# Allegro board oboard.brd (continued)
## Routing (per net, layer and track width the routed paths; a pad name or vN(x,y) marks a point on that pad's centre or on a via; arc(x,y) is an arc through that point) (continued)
LVD17: length 33.2
  TOP w0.127: J2.12 v1(60.59,38.06) ; 55,42.05 54.95,42.05 54.85,41.95 54.84,41.95 54.7,41.81 39.95,41.81 38.4,40.26 U1.72
  TOP w0.2: 55,42.05 55.7,42.75 59.6,42.75 59.8,42.55 59.81,42.55 60.65,41.71 v1(60.65,41.17)
  BOTTOM w0.2: v1(60.59,38.06) 60.65,38.12 v1(60.65,41.17)
LVDE: length 25.9
  TOP w0.127: U1.50 43.69,32.12 44.42,31.39 53.67,31.39 55.57,29.49 v1(59.89,29.49)
  TOP w0.2: J2.34 60.39,27.06 59.89,27.56 v1(59.89,28.47)
  BOTTOM w0.18: v1(59.89,28.47) 59.89,28.8
  BOTTOM w0.2: 59.89,28.8 v1(59.89,29.49)
LVSYNC: length 25.1
  TOP w0.127: 60.65,28.73 60.4,28.98 55.57,28.98 53.41,31.14 44.27,31.14 43.69,31.72 U1.49
  TOP w0.2: J2.33 61.9,27.56 61.73,27.39 61.08,27.39 60.65,27.81 60.65,28.73
MIC_BIAS: length 17.9
  TOP w0.127: U1.95 29.2,40.21 28.62,40.79 26.4,40.79
  TOP w0.2: v1(19.51,40.79) 26.4,40.79
  BOTTOM w0.127: R32.1 20.01,47.86 19.51,47.35 19.51,45.85
  BOTTOM w0.2: v1(19.51,40.79) 19.51,45.85
MIC_INN: length 26.5
  TOP w0.127: U1.98 26.31,37.32 25.25,38.38 18.49,38.38 v1(18.11,38.76)
  BOTTOM w0.127: 18.11,39.71 18.11,46.26 18.07,46.3
  BOTTOM w0.2: 18.07,39.75 C46.1 ; 18.07,39.75 18.07,39.33 18.11,39.29 v1(18.11,38.76) ; 18.07,39.75 18.11,39.71 ; C46.1 17.98,46.85 C48.2 ; C46.1 C50.1
MIC_INP: length 25.7
  TOP w0.127: v1(20.14,38.89) 20.39,38.63 25.48,38.63 26.39,37.72 U1.97
  TOP w0.2: v1(18.91,46.17) v1(20.23,46.17)
  BOTTOM w0.127: 20.14,39.42 20.14,46.26 20.1,46.3 C49.1
  BOTTOM w0.2: v1(18.91,46.17) C46.2 19,46.85 C45.2 ; C49.1 20.23,46.63 v1(20.23,46.17) 20.23,39.51 20.14,39.42 v1(20.14,38.89)
MUTE: length 37.5
  TOP w0.127: 21.05,45.62 22.55,45.62 23.54,46.6 30.97,46.6 v1(31.32,46.25) ; v1(42.75,46.25) v1(39.32,46.25)
  TOP w0.2: 21.05,45.62 9.09,45.62 v1(8.71,46)
  BOTTOM w0.2: R30.2 8.71,45.05 v1(8.71,46) U5.5 ; v1(31.32,46.25) v1(39.32,46.25) ; v1(42.75,46.25) R31.2
NALE: length 29.2
  TOP w0.2: U1.120 17.75,28.52 17.33,28.1 14.37,28.1 14.25,28.22 v1(9.98,28.22)
  BOTTOM w0.127: 10.23,28.47 v1(9.98,28.22) 9.89,28.13 9.89,27.95
  BOTTOM w0.2: U2.17 9.89,27.95
NBUSY0: length 27.2
  TOP w0.127: v1(17.73,30.25) 17.86,30.12 18.46,30.12 18.55,30.03 18.97,30.03 19.06,30.12 U1.116
  BOTTOM w0.127: 14.89,14.2 14.89,14.01
  BOTTOM w0.2: v1(17.73,30.25) 17.73,29.43 14.9,26.6 14.89,26.6 U2.7 14.89,14.2 ; 14.89,14.01 R9.2
NCLE: length 28.4
  TOP w0.2: v1(11.5,28.86) 15.25,28.86 15.55,28.55 16.83,28.55 17.2,28.92 U1.119
  BOTTOM w0.2: v1(11.5,28.86) 10.39,27.74 U2.16
NCS0: length 30.2
  TOP w0.127: 24.6,27.72 22.8,27.72
  TOP w0.2: v1(13.89,14.89) R11.1 ; v1(13.92,27.59) 14.35,27.15 20.08,27.15 20.65,27.72 22.8,27.72 ; U1.122 24.6,27.72
  BOTTOM w0.2: v1(13.92,27.59) 13.89,27.59 13.6,27.3 13.6,17.81 13.89,17.52 U2.9 v1(13.89,14.89)
NCS1: length 28.7
  TOP w0.2: U3.7 23.32,17.3 22.68,16.66 v1(19.38,16.66) ; v1(19.38,27.97) 19.49,27.97 19.65,28.12 U1.121
  BOTTOM w0.2: v1(19.38,27.97) v1(19.38,16.66)
ND0: length 21.6
  TOP w0.2: U1.107 v1(8.62,33.72)
  BOTTOM w0.127: v1(8.62,33.72) 8.62,33.77 8.71,33.68
  BOTTOM w0.2: v1(8.62,33.72) 8.39,33.96 U2.29
ND1: length 21.4
  TOP w0.127: 10.9,33.32 10.05,33.32
  TOP w0.2: v1(9.47,33.17) 9.7,33.17 9.85,33.32 10.05,33.32 ; U1.108 10.9,33.32
  BOTTOM w0.2: v1(9.47,33.17) 9.55,33.25 9.55,34 8.89,34.66 U2.30
ND2: length 20.9
  TOP w0.127: 11.9,32.92 10.75,32.92
  TOP w0.2: U1.109 11.9,32.92 ; 10.75,32.92 10.62,32.79 v1(10.49,32.79)
  BOTTOM w0.2: U2.31 9.39,34.86 10.49,33.76 v1(10.49,32.79)
ND3: length 20.5
  TOP w0.2: U1.110 11.62,32.52 v1(11.5,32.41)
  BOTTOM w0.2: v1(11.5,32.41) 11.5,32.94 11.5,32.95 11.5,33.45 9.89,35.06 U2.32
ND4: length 17.6
  TOP w0.2: v1(14.3,31.9) 14.52,32.12 U1.111
  BOTTOM w0.127: 14.39,32.12 14.3,32.03 v1(14.3,31.9)
  BOTTOM w0.2: U2.41 14.39,32.12
ND5: length 17.3
  TOP w0.2: U1.112 15.26,31.72 v1(15.06,31.52)
  BOTTOM w0.127: v1(15.06,31.52) 15.06,31.65 14.89,31.82
  BOTTOM w0.2: U2.42 14.89,31.82
ND6: length 16.9
  TOP w0.2: U1.113 16.13,31.32 v1(15.95,31.14)
  BOTTOM w0.127: 15.95,31.39 v1(15.95,31.14)
  BOTTOM w0.2: 15.95,31.39 15.39,31.95 U2.43
ND7: length 16.6
  TOP w0.127: U1.114 19.06,30.92 18.97,31.02 18.55,31.02 18.46,30.92 17.13,30.92 v1(16.97,30.76)
  BOTTOM w0.2: U2.44 15.89,32.46 17,31.35 17,30.79 v1(16.97,30.76)
NRE: length 24.5
  TOP w0.127: v1(16.08,29.11) 16.29,29.32 16.45,29.32
  TOP w0.2: U1.118 16.45,29.32
  BOTTOM w0.127: v1(16.08,29.11) 16.33,29.36
  BOTTOM w0.2: v1(16.08,29.11) 16.08,28.58 14.39,26.89 U2.8
NWR: length 30.7
  TOP w0.127: 17.95,29.72 17.51,29.72
  TOP w0.2: v1(9.96,29.72) 17.51,29.72 17.51,29.72 17.95,29.72 17.95,29.72 U1.117
  BOTTOM w0.2: U2.18 9.39,29.15 v1(9.96,29.72)
OUTLM: length 14.1
  TOP w0.2: v1(10.74,51.33) 5.85,51.33 4.71,52.48 J4.2
  BOTTOM w0.2: U5.3 11.25,50.83 v1(10.74,51.33)
OUTLP: length 17.5
  TOP w0.2: v1(12.52,51.84) 12.14,52.22 6.18,52.22 3.38,55.02 J4.1
  BOTTOM w0.2: U5.1 13.79,50.57 v1(12.52,51.84)
OUTRM: length 15.2
  TOP w0.2: v1(11.25,53.87) 11.25,58.06 10.23,59.08 J5.1
  BOTTOM w0.127: U5.14 v1(11.25,53.87)
OUTRP: length 19.5
  TOP w0.2: J5.2 11.38,61.62 13.79,59.21 v1(13.79,53.87)
  BOTTOM w0.127: U5.16 v1(13.79,53.87)
RTC_XIN: length 6
  TOP w0.127: v1(29.54,41.81) 30,41.35 U1.93
  BOTTOM w0.127: 30.81,41.94 30.81,42.19 Y1.1 ; 29.92,42.19 29.88,42.16
  BOTTOM w0.2: 29.92,42.19 Y1.1 31.36,41.64 C2.1 ; 29.88,42.16 v1(29.54,41.81)
RTC_XOUT: length 5.1
  TOP w0.127: U1.94 29.6,40.48 v1(28.02,42.06)
  BOTTOM w0.2: Y1.2 27.47,41.64 C3.1
RTCVDD33: length 8.7
  TOP w0.127: U1.90 31.2,40.66 30.68,41.17 30.68,41.94 30.14,42.48 30.14,44 29.67,44.48 29.09,44.48 R4.1 28.44,43.82 R3.2 27.4,43.82 27.38,43.8 C7.1
SD_CD: length 30
  TOP w0.127: 14.9,24.32 J1.9 ; U1.115 v1(18.76,30.52)
  TOP w0.2: v1(18.76,24.3) 16.6,24.3 16.58,24.32 J1.9 ; 14.9,24.32 14.39,24.32 14.05,24.66 v1(5.79,24.66)
  BOTTOM w0.2: R13.1 3.52,24.66 v1(5.79,24.66) ; v1(18.76,30.52) v1(18.76,24.3)
SD_CLK: length 14.2
  TOP w0.127: 27.25,20.35 v1(26.87,20.35)
  TOP w0.2: v1(26.87,20.35) 19.02,20.35 18.76,20.09 ; U1.4 30,22.8 29.26,22.05 29.23,22.05 28.65,21.47 v1(28.65,20.35)
  BOTTOM w0.2: v1(28.65,20.35) 28.5,20.2 27.1,20.2 26.95,20.35 v1(26.87,20.35)
SD_CMD: length 32.6
  TOP w0.127: U1.3 29.6,22.82 29.1,22.32 28.45,22.32 ; 11.8,17.72 11.93,17.72
  TOP w0.2: v1(26.36,23.01) 27.4,23.01 28.09,22.32 28.45,22.32 ; v1(5.66,19.96) 9.68,19.96 11.82,17.82 ; 11.82,17.82 11.93,17.72 J1.3 17.62,17.72 19.86,19.96 26.11,19.96 v1(26.36,19.71) ; 11.82,17.82 11.82,17.75 11.8,17.72
  BOTTOM w0.2: RN1.2 5.29,20.34 v1(5.66,19.96) ; v1(26.36,19.71) 25.99,20.09 25.99,21.54 26.36,21.91 v1(26.36,23.01)
SD_D0: length 29.8
  TOP w0.127: 26.25,20.85 v1(27.51,20.85)
  TOP w0.2: v1(4.27,21.49) 4.9,22.12 J1.7 21.28,22.12 22.55,20.85 26.25,20.85 ; v1(29.41,20.85) 29.41,21.55 30.4,22.54 U1.5
  BOTTOM w0.2: v1(27.51,20.85) 27.7,20.85 27.9,21.05 29.22,21.05 v1(29.41,20.85) ; v1(4.27,21.49) 4.27,20.98 RN1.1
SD_D1: length 30.7
  TOP w0.2: v1(26.87,21.36) 23,21.36 21.14,23.22 J1.8 14.73,23.22 14.3,23.65 v1(5.79,23.65) ; v1(30.55,21.36) 30.8,21.61 U1.6
  BOTTOM w0.2: R12.1 3.92,23.65 4.05,23.77 5.66,23.77 v1(5.79,23.65) ; v1(30.55,21.36) 30.32,21.6 27.2,21.6 26.96,21.36 v1(26.87,21.36)
SD_D2: length 33.7
  TOP w0.127: v1(24.97,23.9) 27.32,23.9 27.33,23.91 28.14,23.91 28.53,23.52 U1.1 ; 19.61,18.54 20.37,19.31 21.25,19.31
  TOP w0.2: v1(24.97,18.82) 24.48,19.31 21.25,19.31 ; v1(4.14,18.57) 9.47,18.57 12.52,15.52 J1.1 16.59,15.52 19.61,18.54
  BOTTOM w0.2: v1(4.14,18.57) 4.14,19.25 RN1.4 ; v1(24.97,18.82) v1(24.97,23.9)
SD_D3: length 33
  TOP w0.127: U1.2 29.2,22.83 29,22.63 ; v1(25.6,23.27) 25.95,23.62 27.45,23.62
  TOP w0.2: 29,22.63 28.6,22.63 28.59,22.65 28.39,22.65 27.45,23.59 27.45,23.62 ; v1(25.6,19.33) 25.3,19.64 20.09,19.64 17.3,16.85 16,16.85 15.77,16.62 J1.2 12.23,16.62 9.65,19.2 v1(5.28,19.2)
  BOTTOM w0.2: v1(25.6,19.33) v1(25.6,23.27) ; RN1.3 4.64,19.84 v1(5.28,19.2)
SF_CLK: length 17
  TOP w0.127: v1(23.7,23.52) 23.66,23.56 23.66,23.74 25.64,25.72 U1.127 ; v1(23.7,16.54) 23.7,16.41 23.82,16.28
  TOP w0.2: U3.6 24.2,16.03 v1(23.7,16.54)
  BOTTOM w0.2: v1(23.7,23.52) v1(23.7,16.54)
SF_CS: length 47.8
  TOP w0.127: v1(30.94,44.6) 30.72,44.82 ; U1.77 36.4,40.41 36.65,40.67 v1(36.65,44.22) ; 22.55,44.6 v1(20.9,44.6)
  TOP w0.2: 30.72,44.82 29.64,45.9 23.85,45.9 22.55,44.6
  BOTTOM w0.127: v1(20.9,18.7) 20.9,19.1 ; 20.9,24.15 20.9,25.2
  BOTTOM w0.2: v1(36.65,44.22) 36.53,44.1 31.44,44.1 v1(30.94,44.6) ; 20.9,19.1 20.9,24.15 ; 20.9,25.2 v1(20.9,44.6)
SF_DI: length 19.2
  TOP w0.127: v1(23.19,24.16) 23.7,24.16 25.66,26.12 U1.126
  TOP w0.2: U3.5 24.33,14.76 v1(23.19,15.9)
  BOTTOM w0.2: v1(23.19,15.9) 22.9,16.19 22.9,23.75 23.19,24.04 v1(23.19,24.16)
SF_DO: length 15.8
  TOP w0.127: U3.2 20.52,17.3 v1(20.27,17.55) ; U1.124 25.7,26.92 23.95,25.17 v1(20.27,25.17)
  BOTTOM w0.2: v1(20.27,25.17) v1(20.27,17.55)
SPD0: length 21
  TOP w0.127: J3.19 32.96,4.84 32.8,5 32.8,9.44 32.96,9.6 32.96,10.57 32.9,10.62 32.9,10.64 32.46,11.08 32.46,11.58 33.98,13.11 33.98,16.28 35.6,17.9 U1.18
SPD1: length 20.7
  TOP w0.127: U1.17 35.2,17.88 33.72,16.4 33.72,13.23 31.96,11.47 J3.21
SPD2: length 20.8
  TOP w0.127: J3.22 31.46,11.35 33.47,13.36 33.47,16.53 33.97,17.03 33.97,17.03 34.8,17.86 U1.16
SPD3: length 22.5
  TOP w0.127: v1(30.81,10.31) 30.81,11.14 33.22,13.54 33.22,16.63 33.72,17.14 33.72,17.16 34.4,17.84 U1.15 ; J3.20 v1(32.46,10.31)
  BOTTOM w0.127: 32.15,10.31 v1(32.46,10.31)
  BOTTOM w0.2: v1(30.81,10.31) 32.15,10.31
SPD4: length 23.8
  TOP w0.127: 33.46,6.85 33.46,6.89 33.15,7.2 33.15,9.39 33.26,9.5 33.26,10.79 33.09,10.96 v1(33.09,11.46) ; v1(30.55,11.58) 30.68,11.58 32.96,13.86 32.96,16.78 32.98,16.8 33.02,16.8 33.46,17.24 33.46,17.29 34,17.82 U1.14
  TOP w0.2: 33.46,6.85 J3.18
  BOTTOM w0.127: 33.26,11.41 33.22,11.46 v1(33.09,11.46)
  BOTTOM w0.2: v1(30.55,11.58) 32.97,11.58 v1(33.09,11.46)
SPD5: length 24.3
  TOP w0.127: 34.11,9.55 34.11,11.33 v1(34.24,11.46) ; v1(30.55,12.34) 31,12.34 32.71,14.05 32.71,16.91 32.85,17.06 32.92,17.06 33.21,17.35 33.21,17.41 33.6,17.8 U1.13
  TOP w0.2: 34.11,9.55 34.46,9.2 J3.16
  BOTTOM w0.2: v1(34.24,11.46) 33.35,12.34 v1(30.55,12.34)
SPD6: length 25
  TOP w0.2: U1.8 31.6,14.75 29.95,13.1 29.95,10.92 v1(30.05,10.82) ; J3.14 35.46,6.68 34.85,7.29 34.85,9.7 34.62,9.93 v1(34.62,10.31)
  BOTTOM w0.2: v1(34.62,10.31) 34.62,10.57 34.37,10.82 32.98,10.82 32.84,10.96 30.46,10.96 30.32,10.82 v1(30.05,10.82)
SPD7: length 26.5
  TOP w0.127: 36.46,5.8 J3.12
  TOP w0.2: v1(29.3,10.45) 29.3,13.1 31.2,15 U1.7 ; v1(35.89,9.68) 36.46,9.11 36.46,5.8
  BOTTOM w0.2: v1(35.89,9.68) 30.07,9.68 v1(29.3,10.45)
TP_XM: length 24.6
  TOP w0.127: v1(61.56,23.52) 61.16,23.52 59.77,24.92 44.78,24.92 43.98,25.72 U1.34
  TOP w0.2: J2.39 v1(61.56,24.56)
  BOTTOM w0.2: v1(61.56,24.56) v1(61.56,23.52)
TP_XP: length 24.7
  TOP w0.127: U1.36 43.94,26.52 45.03,25.43 60.53,25.43 v1(60.78,25.17)
  TOP w0.2: v1(60.78,26.32) 62.23,26.32 62.4,26.15 62.41,26.15 63,25.56 J2.37
  BOTTOM w0.2: v1(60.78,26.32) v1(60.78,25.17)
TP_YM: length 23.5
  TOP w0.127: J2.40 61.01,24.06 59.89,25.17 44.91,25.17 43.96,26.12 U1.35
TP_YP: length 23.6
  TOP w0.127: U1.37 43.92,26.92 45.16,25.68 61.87,25.68 61.9,25.65 62,25.65 61.9,25.75
  TOP w0.2: J2.38 62.59,25.06 62,25.65
UD_REXT: length 2
  TOP w0.2: v1(41.1,24.92) 41.1,24.49 41.2,24.39 U1.32
  BOTTOM w0.127: R1.1 40.99,25.03 v1(41.1,24.92)
UH_DM: length 73
  TOP w0.2: U1.45 v1(49.98,30.12) ; v1(49.99,46.25) 49.99,46.79 50.35,47.15 50.35,76.35 49.73,76.97 J9.2
  BOTTOM w0.127: 49.98,30.25 49.99,30.25 49.99,45.72
  BOTTOM w0.2: v1(49.99,46.25) 49.99,45.72 49.98,45.72 v1(49.98,30.12)
UH_DP: length 51.5
  TOP w0.127: v1(48.21,29.49) 47.97,29.73 43.7,29.73 43.69,29.72 U1.44
  TOP w0.2: J9.3 47.7,73.7 v1(47.7,46.25)
  BOTTOM w0.2: v1(47.7,46.25) 47.7,30 v1(48.21,29.49)
UH_REXT: length 1.7
  TOP w0.127: U1.42 42.31,28.92 v1(41.6,28.22)
USB_DET: length 30.1
  TOP w0.127: v1(50.49,13.74) R56.2
  TOP w0.2: U1.9 32,14.3 v1(31.7,14)
  BOTTOM w0.2: v1(31.7,14) 32.55,14 32.55,14 50.24,14 v1(50.49,13.74)
USB_DM: length 26.5
  TOP w0.127: 40.72,18.15 40.72,22.08 40,22.8 U1.29
  TOP w0.2: v1(41.35,12.09) 41.01,12.09 40.72,12.38 40.72,18.15
  BOTTOM w0.127: 54.47,12.09 54.94,12.09 55,12.16
  BOTTOM w0.2: v1(41.35,12.09) 54.47,12.09 54.53,12.16 v1(55.07,12.16)
USB_DP: length 27.3
  TOP w0.127: 40.68,22.47 40.4,22.75 40.4,22.78 ; 40.68,22.47 40.68,22.49 40.4,22.78 ; 40.68,22.47 41.35,21.8 ; U1.30 40.4,22.78 ; R55.2 v1(56.46,12.85) ; 41.35,18.8 41.35,17.9
  TOP w0.2: 41.35,21.8 41.35,18.8 ; 41.35,17.9 v1(41.35,12.85)
  BOTTOM w0.2: v1(41.35,12.85) v1(56.46,12.85)
USB_VIN: length 5.7
  TOP w0.127: J10.1 53.37,10.03 D2.2 52.82,10.08 52.81,10.06 52.53,10.06 51.89,10.69 R57.1
XIN: length 6.4
  TOP w0.2: v1(38.56,22.25) 38.4,22.41 U1.25
  BOTTOM w0.127: 38.68,21.87 38.68,21.11
  BOTTOM w0.2: 38.56,22 38.56,21.24 Y2.1 39.99,20.89 C4.1 ; 38.56,22 38.68,21.87 ; 38.56,22 v1(38.56,22.25)
XOUT: length 7.7
  TOP w0.2: U1.24 38,21.08 38.17,20.9 v1(38.17,20.73)
  BOTTOM w0.18: Y2.2 36.19,20.35 35.64,20.89
  BOTTOM w0.2: C5.1 36.1,20.89 Y2.2 37.79,20.35 v1(38.17,20.73)
N04211: length 3.2
  BOTTOM w0.2: U2.19 8.89,14.26 R10.2
N06862: length 2.5
  TOP w0.2: J1.5 17.26,19.92 17.44,20.09 R14.2
N09654: length 3
  TOP w0.2: R11.2 18.41,14.89 19.55,16.03 U3.3
N15646006: length 3.7
  TOP w0.127: 35.76,7.45 R15.2
  TOP w0.2: 35.76,7.45 35.96,7.26 J3.13
N15646070: length 3.7
  TOP w0.127: 33.73,7.4 R16.2
  TOP w0.2: J3.17 33.96,7.04 33.73,7.26 33.73,7.4
N15663479: length 7.2
  TOP w0.127: C52.2 35.89,57.3 33.86,55.27 31.82,55.27 v1(31.57,55.02)
  BOTTOM w0.127: v1(31.57,55.02) 31.82,55.27 32.09,55.27 32.09,55.27 U7.29
N15663486: length 2.5
  TOP w0.127: v1(33.73,56.67) 33.96,56.9 33.96,57.08 33.86,57.18 C55.2
  BOTTOM w0.127: v1(33.73,56.67) 34.13,57.07 34.13,57.62
N15663493: length 4.5
  TOP w0.127: v1(39.7,54.76) 40.33,54.13 40.33,53.62 40.59,53.37 C56.1
  BOTTOM w0.2: v1(39.7,54.76) 39.2,54.27 37.98,54.27
N15663500: length 6.8
  TOP w0.127: v1(31.19,55.78) 33.86,55.78 34.87,56.8 C53.1
  BOTTOM w0.127: v1(31.19,55.78) 32.08,55.78 32.09,55.77 U7.30
N15663575: length 14.1
  TOP w0.127: v1(35.13,51.47) 35.13,54.51 39.32,58.7 R37.2 41.48,58.67 41.48,58.23 41.44,58.19 C59.1 41.44,57.18 41.48,57.13 41.48,56.69 R38.2
  BOTTOM w0.127: 35.13,51.9 U7.21
  BOTTOM w0.2: v1(35.13,51.47) 35.13,51.9
N15663676: length 1.2
  TOP w0.127: R39.2 v1(32.97,57.43)
  BOTTOM w0.127: v1(32.97,57.43) 33.44,57.43 33.63,57.62
N15663702: length 2.7
  TOP w0.127: v1(30.94,57.3) R41.1
  BOTTOM w0.127: U7.32 32.23,56.77 32.08,56.92 31.32,56.92 v1(30.94,57.3)
N15664512: length 7.1
  TOP w0.127: R40.2 31.93,58.69 30.96,58.69 R41.2 30.79,58.72 v1(30.68,58.83) ; C60.2 27.89,59.84 27.62,59.58 27.62,58.22
  BOTTOM w0.127: v1(30.68,58.83) v1(27.63,58.83)
N15664809: length 7.1
  TOP w0.127: R40.1 v1(31.95,56.29) 30.09,56.29 Y3.1 29.7,55.34 C58.2
  BOTTOM w0.127: v1(31.95,56.29) 32.76,56.29 U7.31
N15668493: length 22.1
  TOP w0.127: 39.31,63.27 RN2.1
  TOP w0.2: 39.31,63.27 v1(35,63.27) 36.14,64.41 J8.1
  BOTTOM w0.127: 34.63,62.89 34.63,62.9
  BOTTOM w0.2: 34.63,62.9 v1(35,63.27) ; 34.63,57.62 34.63,62.89
N15668513: length 19.9
  TOP w0.127: 39.06,62.51 38.95,62.51
  TOP w0.2: 39.06,62.51 39.06,62.51 RN2.2 ; J8.2 34.18,71.22 34.18,62.95 34.62,62.51 v1(35.38,62.51) 35.38,62.53 35.55,62.7 38.76,62.7 38.95,62.51
  BOTTOM w0.2: 35.13,57.62 35.13,62.26 v1(35.38,62.51)
N15668525: length 33.9
  TOP w0.127: 33.6,62.51 33.48,62.64 33.48,73.38 33.6,73.51 ; 39.06,62.01 39.06,62 39.02,62
  TOP w0.2: J8.3 33.6,62.51 34.26,61.85 35.85,61.85 36,62 v1(36.14,62) 39.02,62 39.03,62.01 RN2.3
  BOTTOM w0.2: v1(36.14,62) 35.63,61.49 35.63,57.62
N15668529: length 22
  TOP w0.2: J8.6 29.79,65.54 29.75,65.5 33.79,61.46 v1(36.74,61.46) RN2.4
  BOTTOM w0.2: v1(36.74,61.46) 36.13,60.85 36.13,57.62
N15668719: length 14.9
  TOP w0.127: 41.05,75.08 41.1,75.12 41.23,75.12
  TOP w0.2: J8.4 31.06,73.18 J8.5 32.46,75.84 39.87,75.84 40.59,75.13 R35.1 40.61,75.08 41.09,75.08 41.12,75.1 41.21,75.1 41.23,75.12 C57.1
N15674337: length 7.5
  TOP w0.2: R26.1 63.95,10.67 63.9,10.72 R25.2 64.25,11.55 66.2,9.6 SW4.4
N15674345: length 5.8
  TOP w0.2: SW5.4 64.65,3.85 63.95,4.55 R26.2
N15676008: length 2.1
  BOTTOM w0.127: 8.75,54.4 8.71,54.37 8.71,54.33
  BOTTOM w0.2: R24.1 8.75,54.92 8.75,54.37 8.71,54.33 U5.12
N15676062: length 4.6
  BOTTOM w0.2: U5.6 7.44,44.35 8.2,43.59 L4.2
N15676114: length 1.7
  BOTTOM w0.2: R28.1 C40.2
N15676138: length 6.1
  BOTTOM w0.2: U5.7 6.17,44.86 8.77,42.26 R28.2
N15676142: length 5.4
  BOTTOM w0.2: R29.1 6.93,56.41 6.17,55.65 U5.10
N15676150: length 2.8
  BOTTOM w0.2: R29.2 11.25,56.41 11.72,55.94 C41.1
N15676164: length 5.2
  BOTTOM w0.127: C42.2 5.03,42.06
  BOTTOM w0.2: C42.2 4.9,42.28 U5.8
N15687660: length 2.1
  TOP w0.2: C70.2 9.35,71.62 U11.6
N15687760: length 10
  TOP w0.2: C70.1 10.51,73.72 10.91,74.12 L6.1 12.01,75.21 11.49,75.73 7.2,75.73 7.06,75.59 U11.2
N15687792: length 5.1
  TOP w0.2: U11.5 7.06,70.84 6.86,70.64 4.27,70.64 4.01,70.89 R50.2
N15687876: length 3.5
  TOP w0.2: R53.2 7.41,67.94 7.41,69.27 R52.2 R51.2
N15687912: length 2.9
  TOP w0.2: U11.4 5.51,71.62 v1(5.41,71.53)
  BOTTOM w0.2: v1(5.41,71.53) 5.41,69.75 v1(5.66,69.5)
N15691835: length 12.4
  TOP w0.2: D1.2 59.38,51.08 57.48,52.98 v1(53.54,52.98) ; 53.35,48.73 U4.1 53.26,49.2 53.36,49.3 v1(53.36,51.08)
  BOTTOM w0.2: v1(53.36,51.08) 53.36,52.27 53.54,52.45 v1(53.54,52.98)
N15705525: length 4.7
  BOTTOM w0.2: R32.2 21.01,48.69 C44.1 21.05,48.71 21.47,49.12 21.47,49.14 21.48,49.15 R33.1 23.49,50.06 C43.1
N15705529: length 5.8
  BOTTOM w0.2: 18.62,50.06 19,49.68 C45.1 ; 18.62,50.06 C47.2 ; 18.62,50.06 R33.2 20.18,50.16 20.18,51.58 U6.1
N15705631: length 6.1
  BOTTOM w0.2: C47.1 17.56,48.83 17.69,48.71 C48.1 ; C47.1 17.56,51.83 U6.2 ; C47.1 16.01,50.06 R34.2
N15714383: length 4.9
  TOP w0.127: R54.1 55.07,9.93 54.02,8.89 J10.2
N15714387: length 5.3
  TOP w0.127: R55.1 56.46,10.57 54.8,8.9 54.78,8.9 54.67,8.79 J10.3
N15739714: length 36.3
  TOP w0.127: R4.2 29.33,43.01 29.67,42.68 29.67,42.44 30.4,41.71 U1.92
  TOP w0.2: R4.2 28.93,43.11 3.6,43.11 v1(2.62,44.09)
  BOTTOM w0.2: v1(2.62,49.3) v1(2.62,44.09)
N15742573: length 2.9
  TOP w0.127: 61.97,48.88 61.95,48.9 61.91,48.9 ; 63.38,48.84 63.35,48.88 63.31,48.88 ; 61.63,48.93 61.65,48.9 61.69,48.9
  TOP w0.2: Q1.2 63.35,48.84 63.31,48.88 C12.2 61.93,48.88 61.91,48.9 61.69,48.9 61.66,48.93 61.19,48.93 R8.1
N15750041: length 3.5
  TOP w0.127: R58.1 49.2,10.86 50.39,10.86 R56.1 50.49,10.76 R57.2
N15763803: length 4.3
  TOP w0.127: 29.92,4.37 30.14,4.15
  TOP w0.2: R18.2 29.92,4.34 30.1,4.15 J3.24
N15763807: length 3.7
  TOP w0.127: 30.96,7.15 30.96,7.24 30.94,7.26
  TOP w0.2: J3.23 30.96,7.15 30.94,7.17 R17.2
N15841040: length 5.7
  TOP w0.127: J3.4 40.46,3.21 40.46,3.21 40.46,3.2 41.1,2.57 41.88,2.57 44.01,4.7 L13.1
N15841559: length 3.2
  TOP w0.127: L14.1 42.37,6.38 41.46,5.47 J3.2

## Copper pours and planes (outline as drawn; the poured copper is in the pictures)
GND on BOTTOM: 2.98,0 0.88,0.88 0,2.98 0,89.02 0.88,91.12 2.98,92 67.02,92 69.12,91.12 70,89.02 70,2.98 69.12,0.88 67.02,0 ; 38 cut-outs
